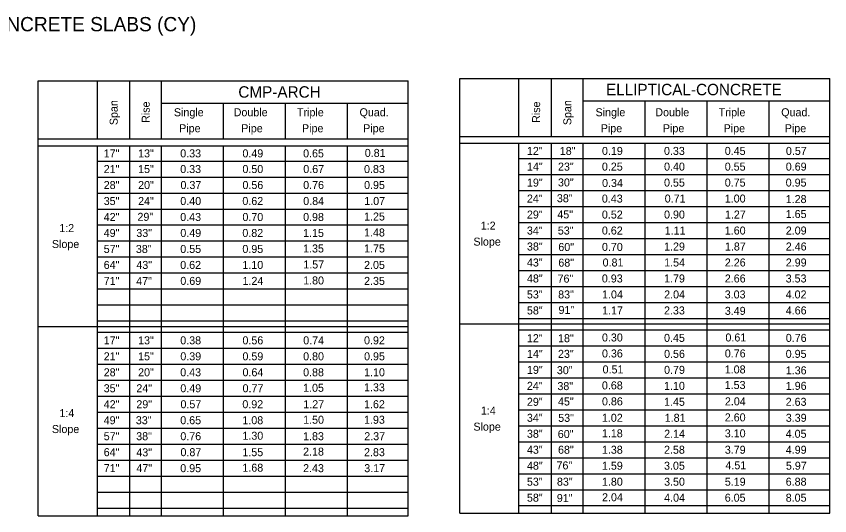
# Model space of a CAD drawing. Extents: x 10064 to 10776, y 10188 to 10407.
# Drawn here: x 10420.2 to 10776, y 10188.2 to 10406.7 of the extents above; entities that cross this region are included whole.
import ezdxf

# ---------------------------------------------------------------- set-up
doc = ezdxf.new("R2010")
doc.units = 0
doc.layers.add('Default', color=7, linetype='Continuous')
doc.layers.add('Dimension', color=7, linetype='Continuous')

msp = doc.modelspace()

# ---------------------------------------------------------------- linework, layer by layer
at = {"layer": 'Default'}
for p, q in [((10614.19, 10189.23), (10614.19, 10379.52)), ((10614.19, 10189.23), (10614.19, 10379.52)), ((10614.19, 10379.52), (10775.96, 10379.52)), ((10640.03, 10354.07), (10640.03, 10379.59)), ((10654.21, 10354.07), (10654.21, 10379.59)), ((10668.18, 10354.07), (10668.18, 10379.59)), ((10775.96, 10189.23), (10775.96, 10379.52)), ((10429.76, 10188.16), (10429.76, 10378.46)), ((10429.76, 10378.46), (10591.54, 10378.46)), ((10455.75, 10353), (10455.75, 10378.53)), ((10469.78, 10353), (10469.78, 10378.53)), ((10483.75, 10353), (10483.75, 10378.53)), ((10591.54, 10188.16), (10591.54, 10378.46)), ((10483.75, 10368.69), (10591.54, 10368.69)), ((10510.78, 10353), (10510.78, 10368.69)), ((10537.99, 10353), (10537.99, 10368.69)), ((10565.06, 10353), (10565.06, 10368.69)), ((10668.18, 10369.76), (10775.96, 10369.76)), ((10695.2, 10354.07), (10695.2, 10369.76)), ((10722.41, 10354.07), (10722.41, 10369.76)), ((10749.49, 10354.07), (10749.49, 10369.76)), ((10614.19, 10354.07), (10775.96, 10354.07)), ((10429.76, 10353), (10591.54, 10353)), ((10614.19, 10351.14), (10775.96, 10351.14)), ((10640.03, 10189.23), (10640.03, 10351.14)), ((10654.21, 10189.23), (10654.21, 10351.14)), ((10668.18, 10189.23), (10668.18, 10351.14)), ((10695.2, 10189.23), (10695.2, 10351.14)), ((10722.41, 10189.23), (10722.41, 10351.14)), ((10749.49, 10189.23), (10749.49, 10351.14)), ((10429.76, 10350.08), (10591.54, 10350.08)), ((10455.75, 10188.16), (10455.75, 10350.08)), ((10469.78, 10188.16), (10469.78, 10350.08)), ((10483.75, 10188.16), (10483.75, 10350.08)), ((10510.78, 10188.16), (10510.78, 10350.08)), ((10537.99, 10188.16), (10537.99, 10350.08)), ((10565.06, 10188.16), (10565.06, 10350.08)), ((10455.75, 10343.35), (10591.54, 10343.35)), ((10640.03, 10344.41), (10775.96, 10344.41)), ((10455.75, 10336.36), (10591.54, 10336.36)), ((10640.03, 10337.42), (10775.96, 10337.42)), ((10455.75, 10329.36), (10591.54, 10329.36)), ((10640.03, 10330.43), (10775.96, 10330.43)), ((10455.75, 10322.37), (10591.54, 10322.37)), ((10640.03, 10323.44), (10775.96, 10323.44)), ((10455.75, 10315.38), (10591.54, 10315.38)), ((10640.03, 10316.45), (10775.96, 10316.45)), ((10455.75, 10308.39), (10591.54, 10308.39)), ((10640.03, 10309.46), (10775.96, 10309.46)), ((10455.75, 10301.4), (10591.54, 10301.4)), ((10640.03, 10302.46), (10775.96, 10302.46)), ((10455.75, 10294.41), (10591.54, 10294.41)), ((10640.03, 10295.47), (10775.96, 10295.47)), ((10455.75, 10287.41), (10591.54, 10287.41)), ((10640.03, 10288.48), (10775.96, 10288.48)), ((10455.75, 10280.42), (10591.54, 10280.42)), ((10640.03, 10281.49), (10775.96, 10281.49)), ((10455.75, 10273.43), (10591.54, 10273.43)), ((10640.03, 10274.5), (10775.96, 10274.5)), ((10429.76, 10271), (10591.54, 10271)), ((10614.19, 10272.06), (10775.96, 10272.06)), ((10640.03, 10269.47), (10775.96, 10269.47)), ((10455.75, 10268.41), (10591.54, 10268.41)), ((10640.03, 10262.48), (10775.96, 10262.48)), ((10455.75, 10261.42), (10591.54, 10261.42)), ((10455.75, 10254.42), (10591.54, 10254.42)), ((10640.03, 10255.49), (10775.96, 10255.49)), ((10455.75, 10247.43), (10591.54, 10247.43)), ((10640.03, 10248.5), (10775.96, 10248.5)), ((10455.75, 10240.44), (10591.54, 10240.44)), ((10640.03, 10241.51), (10775.96, 10241.51)), ((10455.75, 10233.45), (10591.54, 10233.45)), ((10640.03, 10234.52), (10775.96, 10234.52)), ((10455.75, 10226.46), (10591.54, 10226.46)), ((10640.03, 10227.52), (10775.96, 10227.52)), ((10455.75, 10219.47), (10591.54, 10219.47)), ((10640.03, 10220.53), (10775.96, 10220.53)), ((10455.75, 10212.47), (10591.54, 10212.47)), ((10640.03, 10213.54), (10775.96, 10213.54)), ((10455.75, 10205.48), (10591.54, 10205.48)), ((10640.03, 10206.55), (10775.96, 10206.55)), ((10455.75, 10198.49), (10591.54, 10198.49)), ((10640.03, 10199.56), (10775.96, 10199.56)), ((10455.75, 10191.5), (10591.54, 10191.5)), ((10640.03, 10192.57), (10775.96, 10192.57)), ((10429.76, 10188.16), (10591.54, 10188.16)), ((10614.19, 10189.23), (10775.96, 10189.23))]:
    msp.add_line(p, q, dxfattribs=at)

# ---------------------------------------------------------------- texts
at = {"layer": 'Dimension'}
for s, height, p in [('QUANTITIES FOR 3" THICK CONCRETE SLABS (CY)', 6.25, (10293.5, 10400.12)), ('CMP-ARCH', 5, (10517.29, 10371.08)), ('ELLIPTICAL-CONCRETE', 5, (10678.09, 10372.14)), ('Single', 3.5, (10489.11, 10362.95)), ('Double', 3.5, (10515.26, 10362.95)), ('Triple', 3.5, (10542.95, 10362.95)), ('Quad.', 3.5, (10570.31, 10362.95)), ('Single', 3.5, (10673.54, 10362.95)), ('Double', 3.5, (10699.68, 10362.95)), ('Triple', 3.5, (10727.38, 10362.95)), ('Quad.', 3.5, (10754.74, 10362.95)), ('Pipe', 3.5, (10491.41, 10355.95)), ('Pipe', 3.5, (10518.58, 10355.95)), ('Pipe', 3.5, (10545.13, 10355.95)), ('Pipe', 3.5, (10571.9, 10355.95)), ('Pipe', 3.5, (10675.83, 10355.95)), ('Pipe', 3.5, (10703, 10355.95)), ('Pipe', 3.5, (10729.56, 10355.95)), ('Pipe', 3.5, (10756.32, 10355.95)), ('17"', 3.5, (10458.41, 10344.96)), ('13"', 3.5, (10473.45, 10344.96)), ('0.33', 3.5, (10491.88, 10344.96)), ('0.49', 3.5, (10519.08, 10344.96)), ('0.65', 3.5, (10545.62, 10344.96)), ('0.81', 3.5, (10572.59, 10345.16)), ('12"', 3.5, (10643.52, 10346.03)), ('18"', 3.5, (10657.89, 10346.03)), ('0.19', 3.5, (10676.34, 10346.03)), ('0.33', 3.5, (10703.47, 10346.03)), ('0.45', 3.5, (10730.05, 10346.03)), ('0.57', 3.5, (10756.8, 10346.03)), ('21"', 3.5, (10458.41, 10338.1)), ('15"', 3.5, (10473.45, 10338.1)), ('0.33', 3.5, (10491.88, 10338.1)), ('0.50', 3.5, (10519.08, 10338.1)), ('0.67', 3.5, (10545.7, 10338.1)), ('0.83', 3.5, (10572.27, 10338.1)), ('14"', 3.5, (10643.54, 10339.17)), ('23"', 3.5, (10657.1, 10339.17)), ('0.25', 3.5, (10676.32, 10339.17)), ('0.40', 3.5, (10703.5, 10339.17)), ('0.55', 3.5, (10730.05, 10339.17)), ('0.69', 3.5, (10756.74, 10339.17)), ('28"', 3.5, (10458.41, 10331.11)), ('20"', 3.5, (10473.45, 10331.11)), ('0.37', 3.5, (10491.98, 10331.11)), ('0.56', 3.5, (10519.09, 10331.11)), ('0.76', 3.5, (10545.65, 10331.11)), ('0.95', 3.5, (10572.29, 10331.11)), ('19"', 3.5, (10643.54, 10332.18)), ('30"', 3.5, (10657.11, 10332.25)), ('0.34', 3.5, (10676.38, 10331.99)), ('0.55', 3.5, (10703.49, 10332.18)), ('0.75', 3.5, (10730.05, 10332.18)), ('0.95', 3.5, (10756.71, 10332.18)), ('35"', 3.5, (10458.41, 10324.12)), ('24"', 3.5, (10473.45, 10324.12)), ('0.40', 3.5, (10491.91, 10324.12)), ('0.62', 3.5, (10519.05, 10324.12)), ('0.84', 3.5, (10545.68, 10324.12)), ('1.07', 3.5, (10572.37, 10324.12)), ('24"', 3.5, (10643.52, 10325.19)), ('38"', 3.5, (10656.63, 10325.33)), ('0.43', 3.5, (10676.3, 10325.19)), ('0.71', 3.5, (10703.79, 10325.19)), ('1.00', 3.5, (10730.06, 10325.19)), ('1.28', 3.5, (10756.71, 10324.96)), ('1.65', 3.5, (10756.71, 10318.42)), ('42"', 3.5, (10458.41, 10317.13)), ('29"', 3.5, (10473.17, 10317.2)), ('0.43', 3.5, (10491.88, 10317.13)), ('0.70', 3.5, (10519.08, 10317.13)), ('0.98', 3.5, (10545.62, 10317.13)), ('1.25', 3.5, (10572.29, 10317.33)), ('29"', 3.5, (10643.52, 10318.19)), ('45"', 3.5, (10656.83, 10318.26)), ('0.52', 3.5, (10676.31, 10318.19)), ('0.90', 3.5, (10703.5, 10318.19)), ('1.27', 3.5, (10730.13, 10318.19)), ('1:2', 3.5, (10438.96, 10312.29)), ('1:2', 3.5, (10623.32, 10313.35)), ('49"', 3.5, (10458.4, 10310.14)), ('33"', 3.5, (10472.67, 10310.14)), ('0.49', 3.5, (10491.92, 10310.14)), ('0.82', 3.5, (10519.05, 10310.14)), ('1.15', 3.5, (10545.62, 10310.14)), ('1.48', 3.5, (10572.28, 10310.34)), ('34"', 3.5, (10643.52, 10311.2)), ('53"', 3.5, (10657.03, 10311.2)), ('0.62', 3.5, (10676.31, 10311.2)), ('1.11', 3.5, (10703.79, 10311.2)), ('1.60', 3.5, (10730.06, 10311.2)), ('2.09', 3.5, (10756.74, 10311.2)), ('Slope', 3.5, (10435.75, 10305.29)), ('Slope', 3.5, (10620.11, 10306.35)), ('38"', 3.5, (10643.53, 10304.21)), ('1.29', 3.5, (10703.51, 10304.21)), ('1.87', 3.5, (10730.13, 10304.21)), ('2.46', 3.5, (10756.74, 10304.21)), ('57"', 3.5, (10458.41, 10303.14)), ('38"', 3.5, (10472.48, 10303.14)), ('0.55', 3.5, (10491.9, 10303.14)), ('0.95', 3.5, (10519.06, 10303.14)), ('1.35', 3.5, (10545.62, 10303.35)), ('1.75', 3.5, (10572.29, 10303.35)), ('60"', 3.5, (10657.26, 10304)), ('0.70', 3.5, (10676.33, 10304.03)), ('43"', 3.5, (10643.52, 10297.22)), ('68"', 3.5, (10657.26, 10297.15)), ('0.81', 3.5, (10676.62, 10297.22)), ('1.54', 3.5, (10703.55, 10297.22)), ('2.26', 3.5, (10730.08, 10297.22)), ('2.99', 3.5, (10756.74, 10297.22)), ('64"', 3.5, (10458.4, 10296.15)), ('43"', 3.5, (10472.68, 10296.15)), ('0.62', 3.5, (10491.88, 10296.15)), ('1.10', 3.5, (10519.07, 10296.15)), ('1.57', 3.5, (10545.71, 10296.35)), ('2.05', 3.5, (10572.29, 10296.15)), ('48"', 3.5, (10643.54, 10290.23)), ('76"', 3.5, (10656.92, 10290.16)), ('0.93', 3.5, (10676.3, 10290.23)), ('1.79', 3.5, (10703.51, 10290.23)), ('2.66', 3.5, (10730.07, 10290.23)), ('3.53', 3.5, (10756.7, 10290.23)), ('71"', 3.5, (10458.42, 10289.16)), ('47"', 3.5, (10472.61, 10289.07)), ('0.69', 3.5, (10491.92, 10289.16)), ('1.24', 3.5, (10519.12, 10289.16)), ('1.80', 3.5, (10545.64, 10289.36)), ('2.35', 3.5, (10572.29, 10289.16)), ('53"', 3.5, (10643.51, 10283.24)), ('83"', 3.5, (10657.18, 10283.24)), ('1.04', 3.5, (10676.38, 10283.24)), ('2.04', 3.5, (10703.55, 10283.24)), ('3.03', 3.5, (10730.03, 10283.24)), ('4.02', 3.5, (10756.7, 10283.24)), ('58"', 3.5, (10643.53, 10276.24)), ('91"', 3.5, (10657.33, 10276.45)), ('1.17', 3.5, (10676.4, 10276.24)), ('2.33', 3.5, (10703.48, 10276.24)), ('3.49', 3.5, (10730.07, 10276.06)), ('4.66', 3.5, (10756.74, 10276.24)), ('17"', 3.5, (10458.41, 10263.16)), ('13"', 3.5, (10473.45, 10263.16)), ('0.38', 3.5, (10491.89, 10263.16)), ('0.56', 3.5, (10519.09, 10263.16)), ('0.74', 3.5, (10545.68, 10263.16)), ('0.92', 3.5, (10572.27, 10263.16)), ('12"', 3.5, (10643.52, 10264.1)), ('18"', 3.5, (10657.13, 10264.1)), ('0.30', 3.5, (10676.34, 10264.41)), ('0.45', 3.5, (10703.49, 10264.23)), ('0.61', 3.5, (10730.35, 10264.41)), ('0.76', 3.5, (10756.74, 10264.23)), ('21"', 3.5, (10458.41, 10256.17)), ('15"', 3.5, (10473.45, 10256.17)), ('0.39', 3.5, (10491.92, 10256.17)), ('0.59', 3.5, (10519.09, 10256.17)), ('0.80', 3.5, (10545.64, 10256.17)), ('0.95', 3.5, (10572.29, 10256.17)), ('14"', 3.5, (10643.54, 10257.24)), ('23"', 3.5, (10657.1, 10257.24)), ('0.36', 3.5, (10676.35, 10257.42)), ('0.56', 3.5, (10703.51, 10257.24)), ('0.76', 3.5, (10730.07, 10257.42)), ('0.95', 3.5, (10756.71, 10257.24)), ('28"', 3.5, (10458.41, 10249.18)), ('20"', 3.5, (10473.45, 10249.18)), ('0.43', 3.5, (10491.88, 10249.18)), ('0.64', 3.5, (10519.12, 10249.18)), ('0.88', 3.5, (10545.62, 10249.18)), ('1.10', 3.5, (10572.3, 10249.18)), ('19"', 3.5, (10643.54, 10250.25)), ('30"', 3.5, (10656.62, 10250.11)), ('0.51', 3.5, (10676.62, 10250.43)), ('0.79', 3.5, (10703.51, 10250.25)), ('1.08', 3.5, (10730.05, 10250.43)), ('1.36', 3.5, (10756.74, 10250.02)), ('35"', 3.5, (10458.41, 10242.19)), ('24"', 3.5, (10472.68, 10242.19)), ('0.49', 3.5, (10491.92, 10242.19)), ('0.77', 3.5, (10519.14, 10242.19)), ('1.05', 3.5, (10545.62, 10242.39)), ('1.33', 3.5, (10572.27, 10242.59)), ('24"', 3.5, (10643.52, 10243.25)), ('38"', 3.5, (10656.85, 10243.14)), ('0.68', 3.5, (10676.32, 10243.44)), ('1.10', 3.5, (10703.5, 10243.25)), ('1.53', 3.5, (10730.03, 10243.62)), ('1.96', 3.5, (10756.74, 10243.25)), ('42"', 3.5, (10458.41, 10235.2)), ('29"', 3.5, (10472.68, 10235.2)), ('0.57', 3.5, (10491.98, 10235.2)), ('0.92', 3.5, (10519.05, 10235.2)), ('1.27', 3.5, (10545.71, 10235.2)), ('1.62', 3.5, (10572.27, 10235.2)), ('29"', 3.5, (10643.52, 10236.26)), ('45"', 3.5, (10657.11, 10236.4)), ('0.86', 3.5, (10676.35, 10236.45)), ('1.45', 3.5, (10703.49, 10236.26)), ('2.04', 3.5, (10730.11, 10236.45)), ('2.63', 3.5, (10756.7, 10236.26)), ('1:4', 3.5, (10439.03, 10231.33)), ('1:4', 3.5, (10623.38, 10232.4)), ('2.60', 3.5, (10730.06, 10229.45)), ('49"', 3.5, (10458.4, 10228.2)), ('33"', 3.5, (10472.46, 10228.2)), ('0.65', 3.5, (10491.89, 10228.2)), ('1.08', 3.5, (10519.06, 10228.2)), ('1.50', 3.5, (10545.64, 10228.41)), ('1.93', 3.5, (10572.27, 10228.41)), ('34"', 3.5, (10643.52, 10229.27)), ('53"', 3.5, (10657.2, 10229.24)), ('1.02', 3.5, (10676.31, 10229.27)), ('1.81', 3.5, (10703.79, 10229.27)), ('3.39', 3.5, (10756.74, 10229.27)), ('Slope', 3.5, (10435.75, 10224.33)), ('Slope', 3.5, (10620.11, 10225.4)), ('1.18', 3.5, (10676.32, 10222.46)), ('3.10', 3.5, (10730.06, 10222.46)), ('57"', 3.5, (10458.41, 10221.21)), ('38"', 3.5, (10472.62, 10221.21)), ('0.76', 3.5, (10491.92, 10221.21)), ('1.30', 3.5, (10519.08, 10221.42)), ('1.83', 3.5, (10545.61, 10221.21)), ('2.37', 3.5, (10572.37, 10221.21)), ('38"', 3.5, (10643.53, 10222.28)), ('60"', 3.5, (10657.02, 10222.18)), ('2.14', 3.5, (10703.55, 10222.28)), ('4.05', 3.5, (10756.71, 10222.28)), ('43"', 3.5, (10643.52, 10215.29)), ('68"', 3.5, (10657.12, 10215.29)), ('1.38', 3.5, (10676.32, 10215.29)), ('2.58', 3.5, (10703.49, 10215.29)), ('3.79', 3.5, (10730.07, 10215.29)), ('4.99', 3.5, (10756.74, 10215.29)), ('64"', 3.5, (10458.4, 10214.22)), ('43"', 3.5, (10472.68, 10214.15)), ('0.87', 3.5, (10491.98, 10214.22)), ('1.55', 3.5, (10519.06, 10214.22)), ('2.18', 3.5, (10545.62, 10214.47)), ('2.83', 3.5, (10572.27, 10214.22)), ('48"', 3.5, (10643.54, 10208.3)), ('76"', 3.5, (10656.46, 10208.43)), ('1.59', 3.5, (10676.34, 10208.3)), ('3.05', 3.5, (10703.49, 10208.3)), ('4.51', 3.5, (10730.35, 10208.48)), ('5.97', 3.5, (10756.8, 10208.3)), ('71"', 3.5, (10458.42, 10207.23)), ('47"', 3.5, (10472.7, 10207.23)), ('0.95', 3.5, (10491.89, 10207.23)), ('1.68', 3.5, (10519.06, 10207.43)), ('2.43', 3.5, (10545.61, 10207.23)), ('3.17', 3.5, (10572.37, 10207.23)), ('53"', 3.5, (10643.51, 10201.3)), ('83"', 3.5, (10656.65, 10201.32)), ('1.80', 3.5, (10676.34, 10201.3)), ('3.50', 3.5, (10703.51, 10201.3)), ('5.19', 3.5, (10730.07, 10201.3)), ('6.88', 3.5, (10756.71, 10201.3)), ('58"', 3.5, (10643.53, 10194.31)), ('91"', 3.5, (10656.6, 10194.15)), ('2.04', 3.5, (10676.38, 10194.5)), ('4.04', 3.5, (10703.54, 10194.31)), ('6.05', 3.5, (10730.05, 10194.31)), ('8.05', 3.5, (10756.71, 10194.31))]:
    msp.add_text(s, height=height, dxfattribs=at).set_placement(p)
for s, p in [('Span', (10464.51, 10359.07)), ('Rise', (10478.52, 10360.05)), ('Rise', (10649.29, 10360.05)), ('Span', (10662.94, 10359.07))]:
    msp.add_text(s, height=3.5, rotation=90, dxfattribs=at).set_placement(p)

doc.saveas('drawing.dxf')
